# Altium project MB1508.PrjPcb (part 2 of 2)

## Sheet Peripherals.SchDoc: Peripherals
size A4; Date: Not used; ApprovedBy: Not used; CheckedBy: Not used; Author: Not used; CompanyName: STMicroelectronics; DrawnBy: Not used; Engineer: Not used; Organization: Not used; Address1: Not used; Address2: Not used; Address3: Not used; Address4: Not used; DocumentNumber: Not used; Revision: Not used; SheetNumber: 8; SheetTotal: 11
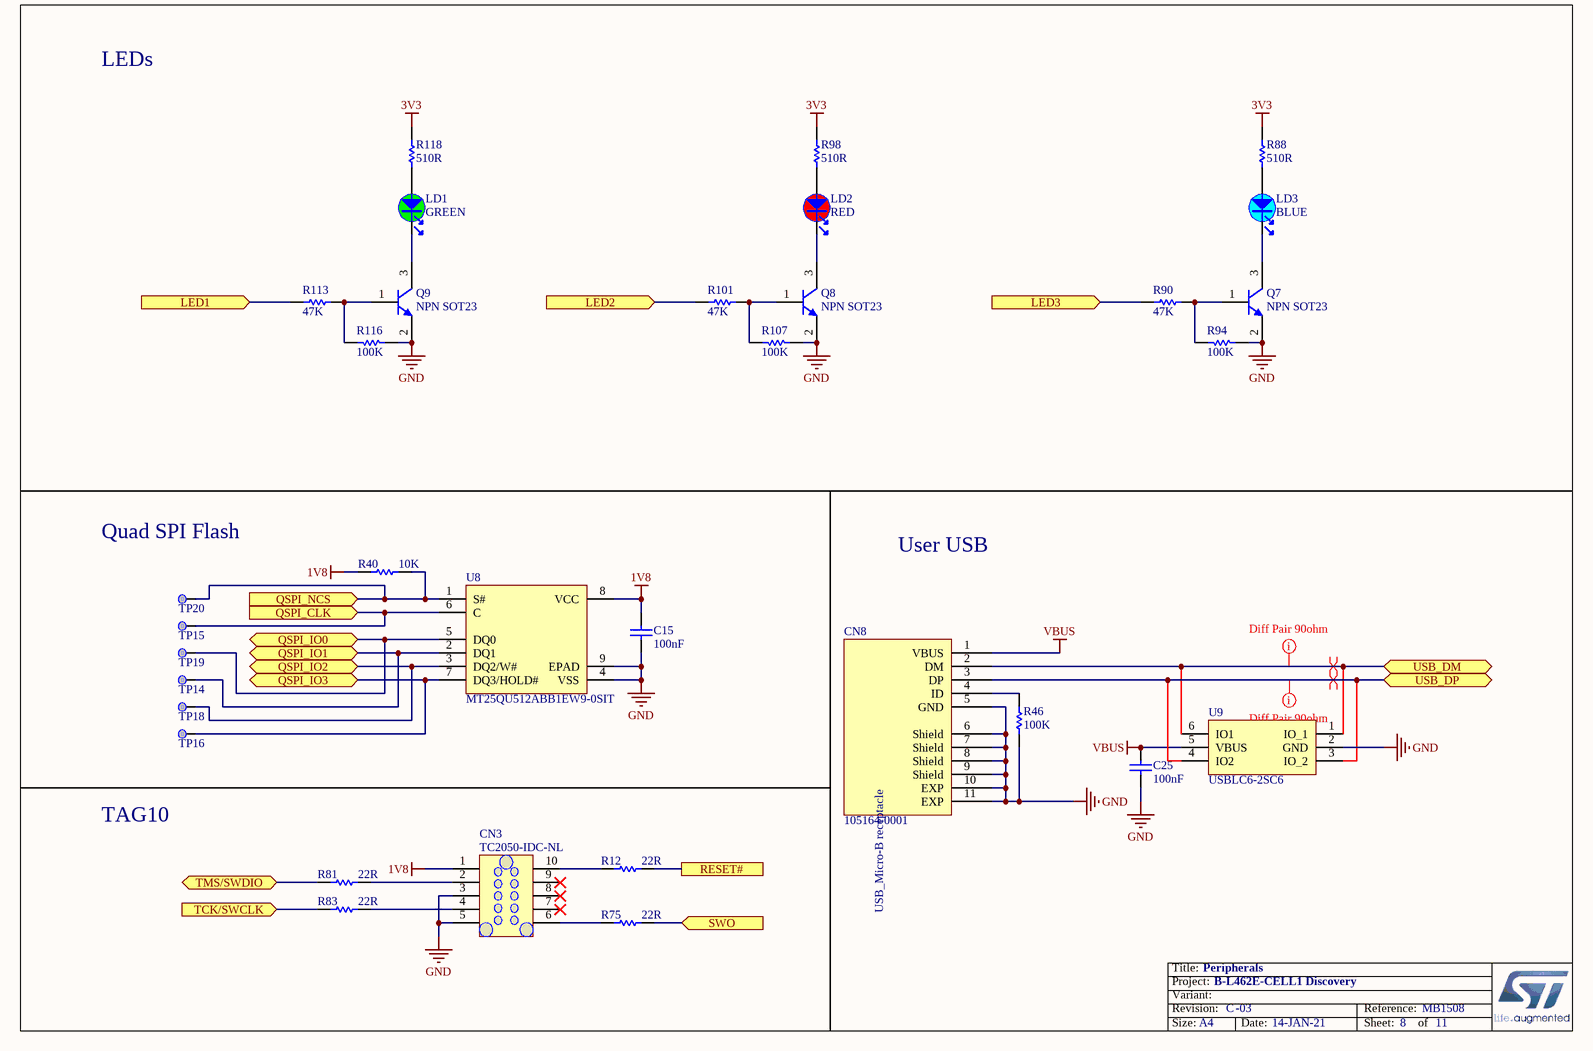
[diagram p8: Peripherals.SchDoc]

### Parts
C15  value 100nF  [C0603]  (hidden comment: Capacitor)
C25  value 100nF  [C0603]  (hidden comment: Capacitor)
CN3  value TC2050-IDC-NL  [CON_TAG-C_TC2050-IDC-NL]  (hidden comment: Tag-10-C)
CN8  value 105164-0001  [CON_USBMICROB_MOLEX_105164-0001_H2P45]  (hidden comment: USB_uB_105164-0001)
LD1  value GREEN  [LED_0603_GREEN_H0P8]  (hidden comment: LED_green)
LD2  value RED  [LED_0603_RED_H0P4]  (hidden comment: LED_red)
LD3  value BLUE  [LED_0603_OSRAM_LB-Q39G-L2OO-35-1_BLUE_1A2K_H0P4]  (hidden comment: LED_blue)
Q7  value NPN SOT23  [NPN_SOT23]  (hidden comment: 9013-SOT23)
Q8  value NPN SOT23  [NPN_SOT23]  (hidden comment: 9013-SOT23)
Q9  value NPN SOT23  [NPN_SOT23]  (hidden comment: 9013-SOT23)
R12  value 22R  [R0603]  (hidden comment: Resistor)
R40  value 10K  [R0603]  (hidden comment: Resistor)
R46  value 100K  [R0603]  (hidden comment: Resistor)
R75  value 22R  [R0603]  (hidden comment: Resistor)
R81  value 22R  [R0603]  (hidden comment: Resistor)
R83  value 22R  [R0603]  (hidden comment: Resistor)
R88  value 510R  [R0603]  (hidden comment: Resistor)
R90  value 47K  [R0603]  (hidden comment: Resistor)
R94  value 100K  [R0603]  (hidden comment: Resistor)
R98  value 510R  [R0603]  (hidden comment: Resistor)
R101  value 47K  [R0603]  (hidden comment: Resistor)
R107  value 100K  [R0603]  (hidden comment: Resistor)
R113  value 47K  [R0603]  (hidden comment: Resistor)
R116  value 100K  [R0603]  (hidden comment: Resistor)
R118  value 510R  [R0603]  (hidden comment: Resistor)
TP14  Test Point  [TP_SMD_1MM]  (value not drawn)  (no BOM)
TP15  Test Point  [TP_SMD_1MM]  (value not drawn)  (no BOM)
TP16  Test Point  [TP_SMD_1MM]  (value not drawn)  (no BOM)
TP18  Test Point  [TP_SMD_1MM]  (value not drawn)  (no BOM)
TP19  Test Point  [TP_SMD_1MM]  (value not drawn)  (no BOM)
TP20  Test Point  [TP_SMD_1MM]  (value not drawn)  (no BOM)
U8  MT25QU512ABB1EW9-0SIT  [ICC_W-PDFN-8_8X6_P127]
U9  USBLC6-2SC6  [ESD_SOT23-6L]

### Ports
LED1 (in), LED2 (in), LED3 (in), QSPI_CLK (in), QSPI_IO0 (bidir), QSPI_IO1 (bidir), QSPI_IO2 (bidir), QSPI_IO3 (bidir), QSPI_NCS (in), RESET#, SWO (in), TCK/SWCLK (in), TMS/SWDIO (bidir), USB_DM (bidir), USB_DP (bidir)

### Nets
1V8: C15.2 CN3.1 R40.1 U8.8(VCC)
3V3: R88.2 R98.2 R118.2
GND: C15.1 C25.1 CN3.3 CN3.5 CN8.5(GND) CN8.6(Shield) CN8.7(Shield) CN8.8(Shield) CN8.9(Shield) CN8.10(EXP) CN8.11(EXP) Q7.2(E) Q8.2(E) Q9.2(E) R46.2 R94.1 R107.1 R116.1 U8.4(VSS) U8.9(EPAD) U9.2(GND)
VBUS: C25.2 CN8.1(VBUS) U9.5(VBUS)
NRST: R12.2 ; port RESET#
PA6: TP16.1 U8.7(DQ3/HOLD#) ; port QSPI_IO3
PA7: TP18.1 U8.3(DQ2/W#) ; port QSPI_IO2
PA11: CN8.2(DM) U9.1(IO_1) U9.6(IO1) ; port USB_DM
PA12: CN8.3(DP) U9.3(IO_2) U9.4(IO2) ; port USB_DP
PA13: R81.1 ; port TMS/SWDIO
PA14: R83.1 ; port TCK/SWCLK
PB0: TP14.1 U8.2(DQ1) ; port QSPI_IO1
PB1: TP19.1 U8.5(DQ0) ; port QSPI_IO0
PB10: TP15.1 U8.6(C) ; port QSPI_CLK
PB14: R90.2 ; port LED3
PB15: R101.2 ; port LED2
PC6: R113.2 ; port LED1
QSPI_NCS: R40.2 TP20.1 U8.1(S#) ; port QSPI_NCS
SWO: R75.2 ; port SWO
NetCN3_2: CN3.2 R81.2
NetCN3_4: CN3.4 R83.2
NetCN3_6: CN3.6 R75.1
NetCN3_10: CN3.10 R12.1
NetCN8_4: CN8.4(ID) R46.1
NetLD1_1: LD1.1 R118.1
NetLD1_2: LD1.2 Q9.3(C)
NetLD2_1: LD2.1 R98.1
NetLD2_2: LD2.2 Q8.3(C)
NetLD3_1: LD3.1 R88.1
NetLD3_2: LD3.2 Q7.3(C)
NetQ7_1: Q7.1(B) R90.1 R94.2
NetQ8_1: Q8.1(B) R101.1 R107.2
NetQ9_1: Q9.1(B) R113.1 R116.2

Not connected (* = marked no-connect by the designer): CN3 7* 8* 9*

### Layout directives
mark named Diff Pair 90ohm: PA11, PA12
differential pair: PA11, PA12

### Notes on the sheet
- LEDs
- Quad SPI Flash
- User USB
- TAG10

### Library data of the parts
C15 = MCD-00237: Capacitor, MLCC, 100nF, 6V3, X5R, +/-10%, 0603, T=0,8mm; Part_Preference: Not recommended; Manufacturer: YAGEO; Manufacturer_Part_Number: CC0603KRX5R5BB104
C25 = MCD-00211: Capacitor, MLCC, 100nF, 16V, X7R, +/-10%, 0603, T=0,8mm; Part_Preference: Recommended; Manufacturer: YAGEO; Manufacturer_Part_Number: CC0603KRX7R7BB104; Order_Code_RS: 669-8763
CN3 = MCD-00031: Tag_Connector Header, 10x2, No legs; Part_Preference: Recommended; Manufacturer: TAG-CONNECT LLC; Manufacturer_Part_Number: TC2050-IDC-NL-FP
CN8 = MCD-01698: Micro-USB B Receptacle without Flange, Top Mount, Surface Mount, Lead-Free; Part_Type: Connector; Part_Preference: Recommended; Manufacturer: MOLEX
LD1 = MCD-00320: LED, Green, 0603; Part_Type: Display; Part_Preference: Not recommended; Manufacturer: EVERLIGHT; Manufacturer_Part_Number: 19-213SYGC/S530-E2/TR8
LD2 = MCD-00322: LED, Red, 0603; Part_Type: Display; Part_Preference: Recommended; Manufacturer: EVERLIGHT; Manufacturer_Part_Number: 19-217/R6C-AL1M2VY/3T
LD3 = MCD-00585: LED Blue, 0603 SMD, Forward Voltage Min=2,8V, Max=3,8V; Part_Type: Display; Part_Preference: Recommended; Manufacturer: OSRAM OPTO SEMICONDUCTORS; Manufacturer_Part_Number: LB Q39G-L2OO-35-1; Alternate_Manufacturer: EVERLIGHT; Alternate_Manufacturer_Part_Number: 19-217-BHC-ZL1M2RY-3T-V4; Order_Code_RS: 9148643
Q7-Q9 = MCD-00073: NPN Bipolar Transistor; Part_Type: IC; Part_Preference: Recommended; Manufacturer: ON SEMICONDUCTOR; Manufacturer_Part_Number: BSR14; Alternate_Manufacturer_Part_Number: MMBT2222LT1G / MMBT2222ALT1G / MMBT2222ALT3G
R12 R75 R81 R83 = MCD-00190: Resistor,22R,0603,1%,1/10W; Part_Preference: Not recommended; Manufacturer: YAGEO; Manufacturer_Part_Number: RC0603FR-0722RL
R40 = MCD-00220: Resistor,10K,0603,1%,1/10W; Part_Preference: Recommended; Manufacturer: YAGEO; Manufacturer_Part_Number: RC0603FR-0710KL
R46 R94 R107 R116 = MCD-00223: Resistor,100K,0603,1%,1/10W; Part_Preference: Recommended; Manufacturer: YAGEO; Manufacturer_Part_Number: RC0603FR-07100KL
R88 R98 R118 = MCD-00225: Resistor,510R,0603,1%,1/10W; Part_Preference: Recommended; Manufacturer: YAGEO; Manufacturer_Part_Number: RC0603FR-07510RL
R90 R101 R113 = MCD-00222: Resistor,47K,0603,1%,1/10W; Part_Preference: Recommended; Manufacturer: YAGEO; Manufacturer_Part_Number: RC0603FR-0747KL
TP14-TP16 TP18-TP20 = MCD-00074: Test Point 1mm; Part_Type: Misc; Part_Preference: Recommended
U8 = MCD-01749: 512Mb, 1.8V Multiple I/O Serial Flash Memory; BMS_Part_Number: 9171981; Part_Type: IC; Part_Preference: Recommended; Manufacturer: MICRON
U9 = MCD-00163: Very low capacitance ESD protection; BMS_Part_Number: 9151075; Part_Type: IC; Part_Preference: Recommended; Manufacturer: STMICROELECTRONICS; Manufacturer_HQ_COO: EU

## Sheet Sensors & LCD.SchDoc: Sensors & LCD
size A4; Date: Not used; ApprovedBy: Not used; CheckedBy: Not used; Author: Not used; CompanyName: STMicroelectronics; DrawnBy: Not used; Engineer: Not used; Organization: Not used; Address1: Not used; Address2: Not used; Address3: Not used; Address4: Not used; DocumentNumber: Not used; Revision: Not used; SheetNumber: 9; SheetTotal: 11
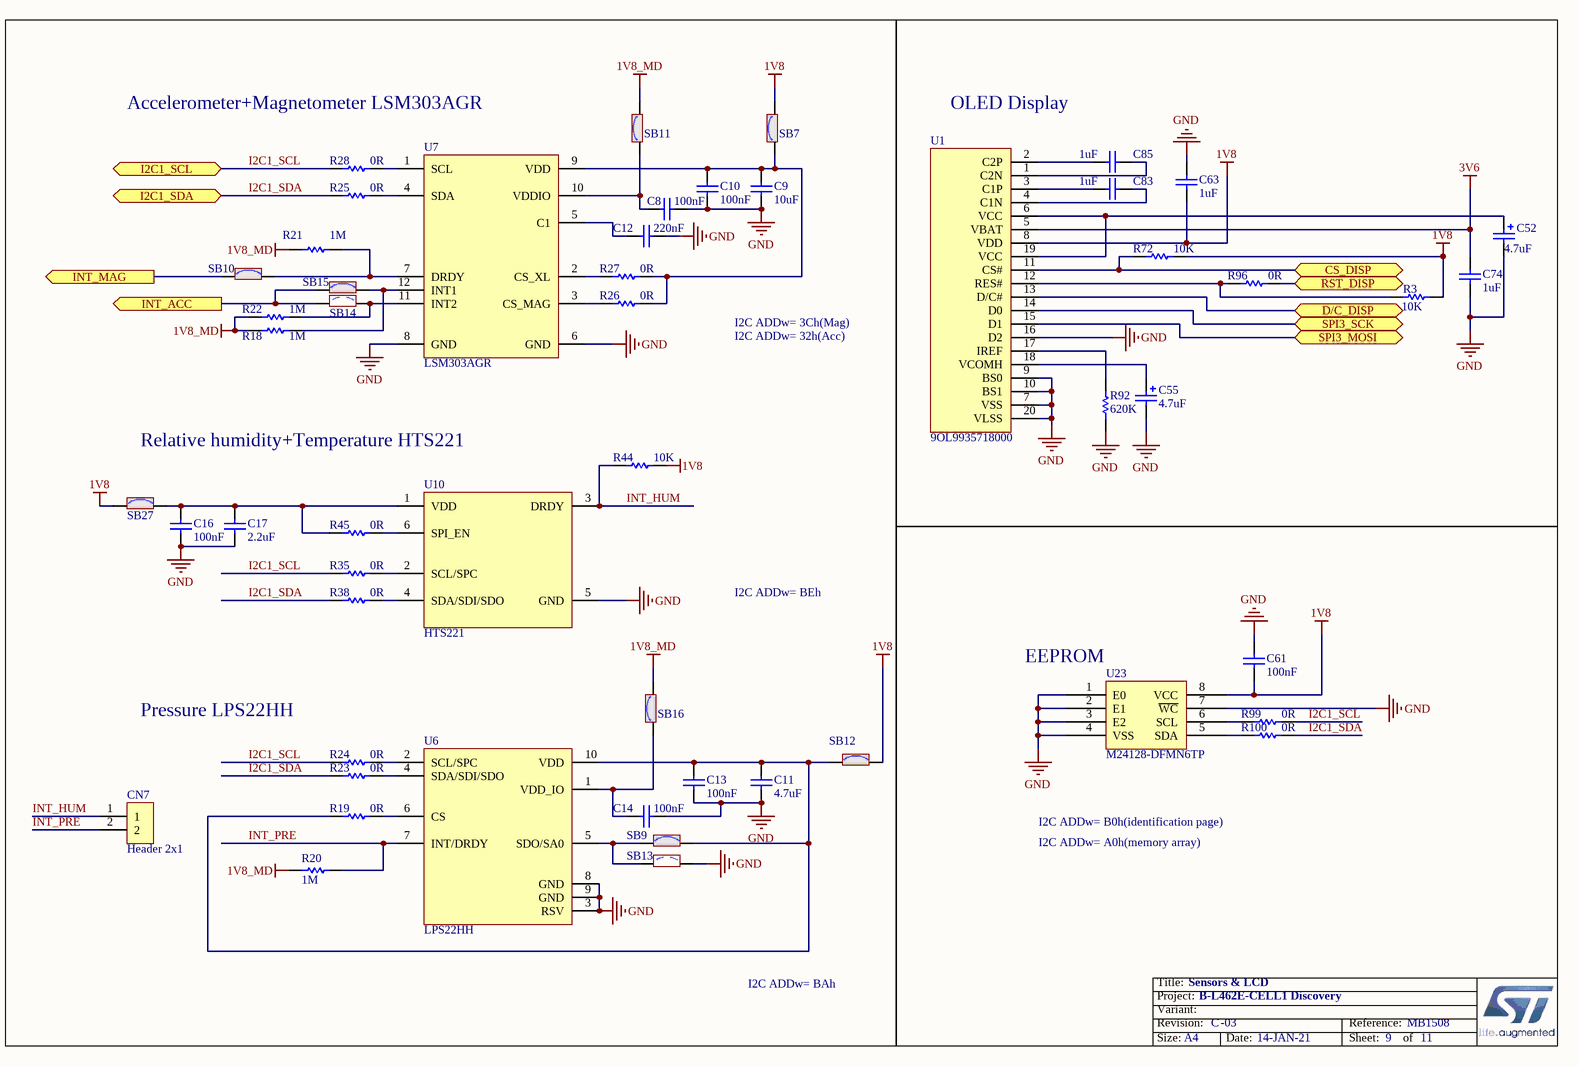
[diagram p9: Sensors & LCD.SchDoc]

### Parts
C8  value 100nF  [C0603]  (hidden comment: Capacitor)
C9  value 10uF  [C0603]  (hidden comment: Capacitor)
C10  value 100nF  [C0603]  (hidden comment: Capacitor)
C11  value 4.7uF  [C0603]  (hidden comment: Capacitor)
C12  value 220nF  [C0402]  (hidden comment: Capacitor)
C13  value 100nF  [C0603]  (hidden comment: Capacitor)
C14  value 100nF  [C0603]  (hidden comment: Capacitor)
C16  value 100nF  [C0603]  (hidden comment: Capacitor)
C17  value 2.2uF  [C0603]  (hidden comment: Capacitor)
C52  value 4.7uF  [CPOL_TAJ-A_1206_H180]  (hidden comment: Cap_POL_TANA)
C55  value 4.7uF  [CPOL_TAJ-A_1206_H180]  (hidden comment: Cap_POL_TANA)
C61  value 100nF  [C0603]  (hidden comment: Capacitor)
C63  value 1uF  [C0603]  (hidden comment: Capacitor)
C74  value 1uF  [C0603]  (hidden comment: Capacitor)
C83  value 1uF  [C0603]  (hidden comment: Capacitor)
C85  value 1uF  [C0603]  (hidden comment: Capacitor)
CN7  Header 2x1  [CON_SAMTEC_TSW-102-08-G-S]
R3  value 10K  [R0603]  (hidden comment: Resistor)
R18  value 1M  [R0603]  (hidden comment: Resistor)
R19  value 0R  [R0603]  (hidden comment: Resistor)
R20  value 1M  [R0603]  (hidden comment: Resistor)
R21  value 1M  [R0603]  (hidden comment: Resistor)
R22  value 1M  [R0603]  (hidden comment: Resistor)
R23  value 0R  [R0603]  (hidden comment: Resistor)
R24  value 0R  [R0603]  (hidden comment: Resistor)
R25  value 0R  [R0603]  (hidden comment: Resistor)
R26  value 0R  [R0603]  (hidden comment: Resistor)
R27  value 0R  [R0603]  (hidden comment: Resistor)
R28  value 0R  [R0603]  (hidden comment: Resistor)
R35  value 0R  [R0603]  (hidden comment: Resistor)
R38  value 0R  [R0603]  (hidden comment: Resistor)
R44  value 10K  [R0603]  (hidden comment: Resistor)
R45  value 0R  [R0603]  (hidden comment: Resistor)
R72  value 10K  [R0603]  (hidden comment: Resistor)
R92  value 620K  [R0603]  (hidden comment: Resistor)
R96  value 0R  [R0603]  (hidden comment: Resistor)
R99  value 0R  [R0603]  (hidden comment: Resistor)
R100  value 0R  [R0603]  (hidden comment: Resistor)
SB7  SB_ON  [SOLDER-BRIDGE_R0603-0R]  (value not drawn)
SB9  SB_ON  [SOLDER-BRIDGE_R0603-0R]  (value not drawn)
SB10  SB_ON  [SOLDER-BRIDGE_R0603-0R]  (value not drawn)
SB11  SB_ON  [SOLDER-BRIDGE_R0603-0R]  (value not drawn)
SB12  SB_ON  [SOLDER-BRIDGE_R0603-0R]  (value not drawn)
SB13  SB_OFF  [SOLDER-BRIDGE_R0603-0R]  (value not drawn)
SB14  SB_OFF  [SOLDER-BRIDGE_R0603-0R]  (value not drawn)
SB15  SB_ON  [SOLDER-BRIDGE_R0603-0R]  (value not drawn)
SB16  SB_ON  [SOLDER-BRIDGE_R0603-0R]  (value not drawn)
SB27  SB_ON  [SOLDER-BRIDGE_R0603-0R]  (value not drawn)
U1  value 9OL9935718000  [OLED_RITDISPLAY_9OL9935718000]  (hidden comment: OLED_RITDISPLAY_9OL9935718000)
U6  LPS22HH  [ICC_HLGA10_2X2_P050]
U7  LSM303AGR  [ICC_LGA12_2X2_P050]
U10  HTS221  [ICC_HLGA6_2X2_P075-1]
U23  M24128-DFMN6TP  [ICC_SO8_5X4_P127]

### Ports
CS_DISP (bidir), D/C_DISP (bidir), I2C1_SCL (bidir), I2C1_SDA (bidir), INT_ACC (out), INT_MAG (out), RST_DISP (bidir), SPI3_MOSI (bidir), SPI3_SCK (bidir)

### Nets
1V8: C61.1 C63.1 R3.1 R44.2 R72.2 SB7.2 SB12.2 SB27.1 U1.8(VDD) U23.8(VCC)
1V8_MD: R18.1 R20.1 R21.1 R22.1 SB11.2 SB16.2
3V6: C74.2 U1.5(VBAT)
GND: C8.1 C9.1 C10.1 C11.2 C12.2 C13.1 C14.1 C16.1 C17.2 C52.2 C55.2 C61.2 C63.2 C74.1 R92.1 SB13.2 U1.7(VSS) U1.9(BS0) U1.10(BS1) U1.16(D2) U1.20(VLSS) U6.3(RSV) U6.8(GND) U6.9(GND) U7.6(GND) U7.8(GND) U10.5(GND) U23.1(E0) U23.2(E1) U23.3(E2) U23.4(VSS) U23.7(~{WC})
I2C1_SCL: R24.1 R28.1 R35.1 R99.2 ; port I2C1_SCL
I2C1_SDA: R23.1 R25.1 R38.1 R100.2 ; port I2C1_SDA
INT_HUM: CN7.1 R44.1 U10.3(DRDY)
INT_PRE: CN7.2 R20.2 U6.7(INT/DRDY)
PB2_R: R72.1 U1.11(CS#) ; port CS_DISP
PC2: SB14.1 SB15.1 ; port INT_ACC
PC3: SB10.1 ; port INT_MAG
PC10: U1.14(D0) ; port SPI3_SCK
PC11: U1.13(D/C#) ; port D/C_DISP
PC12: U1.15(D1) ; port SPI3_MOSI
PH1: R96.2 ; port RST_DISP
NetC8_2: C8.2 SB11.1 U7.10(VDDIO)
NetC9_2: C9.2 C10.2 R26.2 R27.2 SB7.1 U7.9(VDD)
NetC11_1: C11.1 C13.2 R19.1 SB9.2 SB12.1 U6.10(VDD)
NetC12_1: C12.1 U7.5(C1)
NetC14_2: C14.2 SB16.1 U6.1(VDD_IO)
NetC16_2: C16.2 C17.1 R45.1 SB27.2 U10.1(VDD)
NetC52_1: C52.1 U1.6(VCC) U1.19(VCC)
NetC55_1: C55.1 U1.18(VCOMH)
NetC83_1: C83.1 U1.3(C1P)
NetC83_2: C83.2 U1.4(C1N)
NetC85_1: C85.1 U1.2(C2P)
NetC85_2: C85.2 U1.1(C2N)
NetR3_2: R3.2 R96.1 U1.12(RES#)
NetR18_2: R18.2 SB15.2 U7.12(INT1)
NetR19_2: R19.2 U6.6(CS)
NetR21_2: R21.2 SB10.2 U7.7(DRDY)
NetR22_2: R22.2 SB14.2 U7.11(INT2)
NetR23_2: R23.2 U6.4(SDA/SDI/SDO)
NetR24_2: R24.2 U6.2(SCL/SPC)
NetR25_2: R25.2 U7.4(SDA)
NetR26_1: R26.1 U7.3(CS_MAG)
NetR27_1: R27.1 U7.2(CS_XL)
NetR28_2: R28.2 U7.1(SCL)
NetR35_2: R35.2 U10.2(SCL/SPC)
NetR38_2: R38.2 U10.4(SDA/SDI/SDO)
NetR45_2: R45.2 U10.6(SPI_EN)
NetR92_2: R92.2 U1.17(IREF)
NetR99_1: R99.1 U23.6(SCL)
NetR100_1: R100.1 U23.5(SDA)
NetSB9_1: SB9.1 SB13.1 U6.5(SDO/SA0)

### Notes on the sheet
- Accelerometer+Magnetometer LSM303AGR
- OLED Display
- I2C ADDw= 3Ch(Mag)
- I2C ADDw= 32h(Acc)
- Relative humidity+Temperature HTS221
- I2C ADDw= BEh
- (near U23) EEPROM
- Pressure LPS22HH
- I2C ADDw= A0h(memory array)
- I2C ADDw= B0h(identification page)
- I2C ADDw= BAh

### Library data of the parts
C8 C10 C13 C14 C16 C61 = MCD-00237: as C15 on sheet Peripherals
C9 = MCD-00243: Capacitor, MLCC, 10uF, 6V3, X5R, +/-10%, 0603, T=0,8mm; Part_Preference: Recommended; Manufacturer: YAGEO; Manufacturer_Part_Number: CC0603KRX5R5BB106
C11 = MCD-00009: Capacitor, MLCC, 4.7uF, 16V, X5R, +/-10%, 0603, T=0.8mm; Part_Preference: Recommended; Manufacturer: YAGEO; Manufacturer_Part_Number: CC0603KRX5R7BB475
C12 = MCD-00602: Capacitor, MLCC, 220nF, 16V, X7R, +/-10%, ,0402, T=0,5mm; Part_Preference: Recommended; Manufacturer: TDK; Manufacturer_Part_Number: C1005X7R1C224K050BE
C17 = MCD-00012: Capacitor, MLCC, 2.2uF, 10V, X5R, +/- 10%, 0603, T=0,8mm; BMS_Part_Number: 9142010; Part_Preference: Recommended; Manufacturer: YAGEO; Manufacturer_Part_Number: CC0603KRX5R6BB225; Alternate_Manufacturer: KEMET; Alternate_Manufacturer_Part_Number: C0603C225K8PACTU
C52 C55 = MCD-00007: Capacitor, Tantalum, 4.7uF, 16V, 4ohms, +/-10%, pkg Type_A (3216 metric), T=1.6mm; Part_Preference: Recommended; Manufacturer: AVX; Manufacturer_Part_Number: TAJA475K016R; Order_Code_RS: 464-9132
C63 C74 C83 C85 = MCD-00010: Capacitor, MLCC, 1uF, 16V, X5R, +/-10%, 0603, T=0,8mm; Part_Preference: Recommended; Manufacturer: YAGEO; Manufacturer_Part_Number: CC0603KRX5R7BB105
CN7 = MCD-01581: Header 2x1, 2.54mm, VR, TH, height 5.84mm/5.08 mm, height total 13.46 mm; Part_Type: Connector; Part_Preference: Recommended; Manufacturer: SAMTEC; Manufacturer_Part_Number: TSW-102-08-G-S
R3 R44 R72 = MCD-00220: as R40 on sheet Peripherals
R18 R20-R22 = MCD-00257: Resistor,1M,0603,1%,1/10W; Part_Preference: Recommended; Manufacturer: YAGEO; Manufacturer_Part_Number: RC0603FR-071ML
R19 R23-R28 R35 R38 R45 R96 R99 R100 = MCD-00056: Resistor,0R,0603,5%,1/10W; Part_Preference: Recommended; Manufacturer: YAGEO; Manufacturer_Part_Number: RC0603JR-070RL
R92 = MCD-00506: Resistor,620K,0603,1%,1/10W; Part_Preference: Recommended; Manufacturer: YAGEO; Manufacturer_Part_Number: RC0603FR-07620KL
SB7 SB9-SB12 SB15 SB16 SB27 = MCD-00071: Solder Bridge ON; Part_Type: Misc; Part_Preference: Recommended; Manufacturer: YAGEO; Manufacturer_Part_Number: RC0603JR-070RL
SB13 SB14 = MCD-00072: Solder Bridge OFF; Part_Type: Misc; Part_Preference: Recommended; Manufacturer: YAGEO; Manufacturer_Part_Number: RC0603JR-070RL
U1 = MCD-01925: 128*64 Dots 20-pin OLED display; Part_Preference: Recommended; Alternate_Manufacturer_Part_Number: 9OL9935701000
U6 = MCD-01702: High-performance MEMS nano pressure sensor:260-1260 hPa absolute digital output barometer; Part_Type: IC; Part_Preference: Recommended; Manufacturer: STMICROELECTRONICS; Manufacturer_HQ_COO: EU; Component_Country_Of_Origin: France, Malta
U7 = MCD-00709: 3D accelerometer and 3D magnetometer; BMS_Part_Number: 9177057; Part_Type: IC; Part_Preference: Recommended; Manufacturer: STMICROELECTRONICS; Manufacturer_HQ_COO: EU
U10 = MCD-01447: Capacitive digital sensor for relative humidity and temperature; BMS_Part_Number: 9188011; Part_Type: IC; Part_Preference: Recommended; Manufacturer: STMICROELECTRONICS; Manufacturer_HQ_COO: EU
U23 = MCD-00293: I2C memory; BMS_Part_Number: 9175659; Part_Type: IC; Part_Preference: Recommended; Manufacturer: STMICROELECTRONICS; Manufacturer_HQ_COO: EU

## Sheet ST_LINK_V2-1.SchDoc: ST_LINK_V2-1
size A4; Date: Not used; ApprovedBy: Not used; CheckedBy: Not used; Author: Not used; CompanyName: STMicroelectronics; DrawnBy: Not used; Engineer: Not used; Organization: Not used; Address1: Not used; Address2: Not used; Address3: Not used; Address4: Not used; DocumentNumber: Not used; Revision: Not used; SheetNumber: 10; SheetTotal: 11
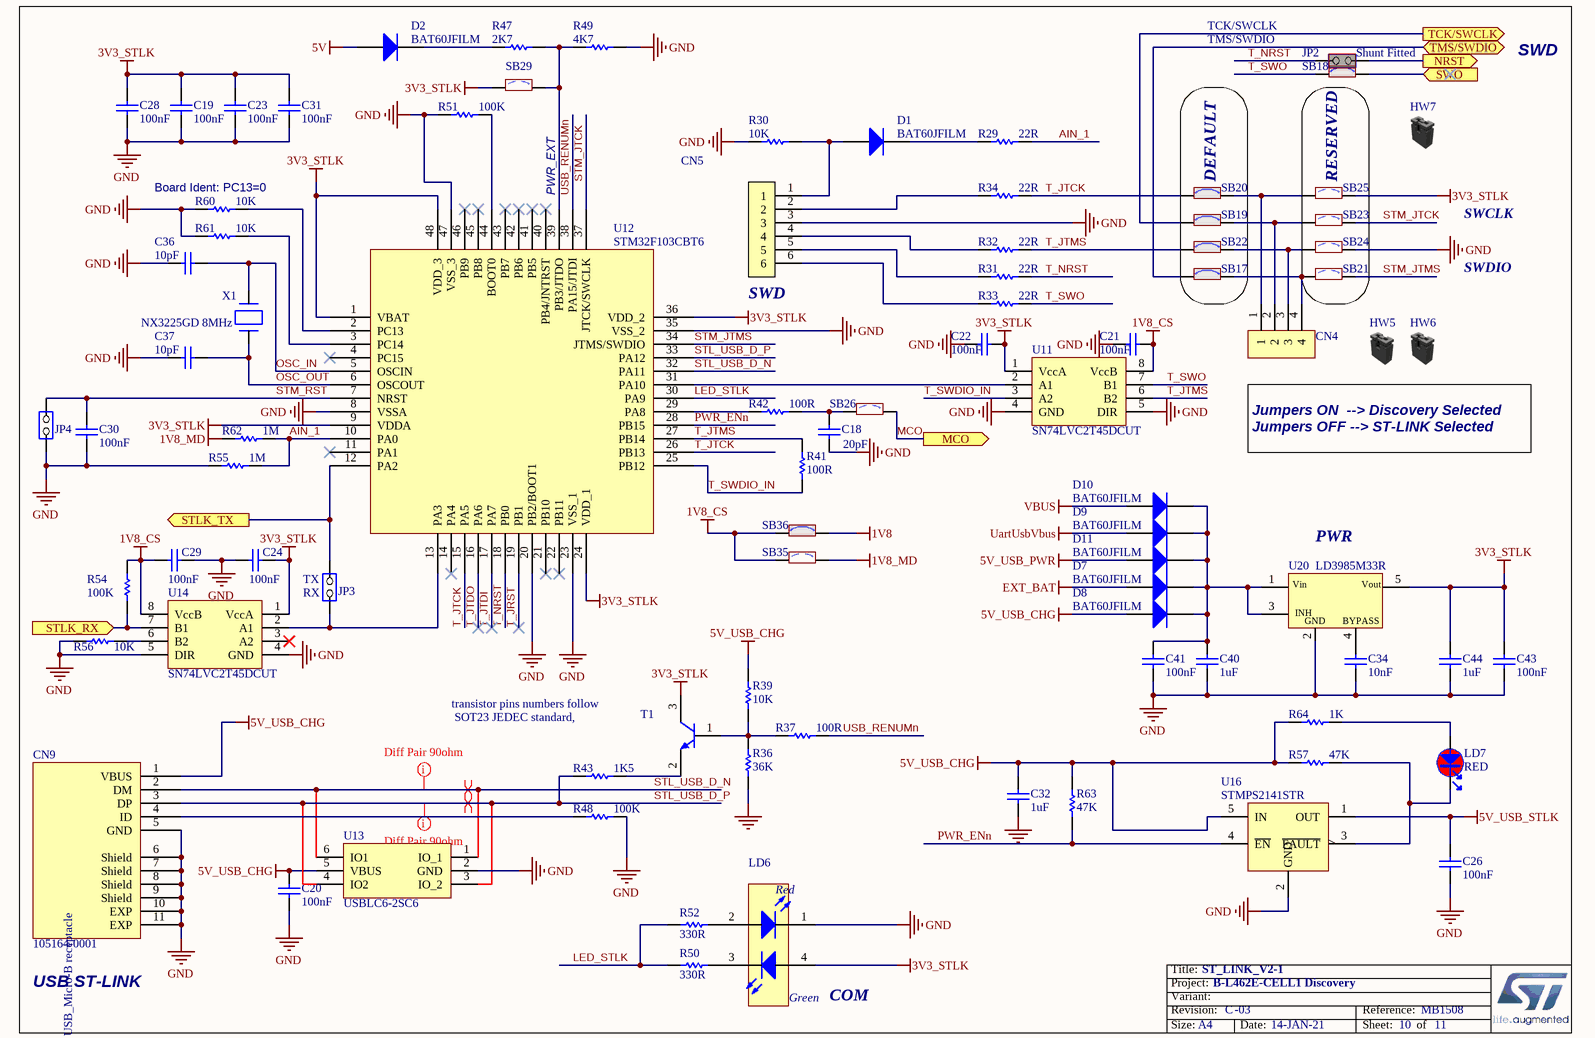
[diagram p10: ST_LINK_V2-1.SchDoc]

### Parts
C18  value 20pF  [C0603]  (hidden comment: Capacitor)
C19  value 100nF  [C0603]  (hidden comment: Capacitor)
C20  value 100nF  [C0603]  (hidden comment: Capacitor)
C21  value 100nF  [C0603]  (hidden comment: Capacitor)
C22  value 100nF  [C0603]  (hidden comment: Capacitor)
C23  value 100nF  [C0603]  (hidden comment: Capacitor)
C24  value 100nF  [C0603]  (hidden comment: Capacitor)
C26  value 100nF  [C0603]  (hidden comment: Capacitor)
C28  value 100nF  [C0603]  (hidden comment: Capacitor)
C29  value 100nF  [C0603]  (hidden comment: Capacitor)
C30  value 100nF  [C0603]  (hidden comment: Capacitor)
C31  value 100nF  [C0603]  (hidden comment: Capacitor)
C32  value 1uF  [C0603]  (hidden comment: Capacitor)
C34  value 10nF  [C0603]  (hidden comment: Capacitor)
C36  value 10pF  [C0603]  (hidden comment: Capacitor)
C37  value 10pF  [C0603]  (hidden comment: Capacitor)
C40  value 1uF  [C0603]  (hidden comment: Capacitor)
C41  value 100nF  [C0603]  (hidden comment: Capacitor)
C43  value 100nF  [C0603]  (hidden comment: Capacitor)
C44  value 1uF  [C0603]  (hidden comment: Capacitor)
CN4  Header 4x1  [CON_988-JIUBABA_PHFS25-11-04-G0B115-T-1]  (value not drawn)
CN5  Header 6x1  [CON_988-JIUBABA_PHFS25-11-06-G0B115-T-1]  (value not drawn)
CN9  value 105164-0001  [CON_USBMICROB_MOLEX_105164-0001_H2P45]  (hidden comment: USB_uB_105164-0001)
D1  BAT60JFILM  [DIO_SOD323]
D2  BAT60JFILM  [DIO_SOD323]
D7  BAT60JFILM  [DIO_SOD323]
D8  BAT60JFILM  [DIO_SOD323]
D9  BAT60JFILM  [DIO_SOD323]
D10  BAT60JFILM  [DIO_SOD323]
D11  BAT60JFILM  [DIO_SOD323]
HW5  Shunt Black 2.54mm  (value not drawn)  (mechanical)
HW6  Shunt Black 2.54mm  (value not drawn)  (mechanical)
HW7  Shunt Black 2.54mm  (value not drawn)  (mechanical)
JP2  value Shunt Fitted  [CON_SAMTEC_TSW-102-07-G-S]  (hidden comment: Jumper_Header 2x1 Fitted)
JP3  Jumper_Header 2x1  [CON_SAMTEC_TSW-102-07-G-S]  (value not drawn)
JP4  Jumper_Header 2x1  [CON_SAMTEC_TSW-102-07-G-S]  (value not drawn)
LD6  LD_BICOLOR_CMS  [LED_BI-GR_HSMF-A201-A00J1]  (value not drawn)
LD7  value RED  [LED_0603_RED]  (hidden comment: LED_red)
R29  value 22R  [R0603]  (hidden comment: Resistor)
R30  value 10K  [R0603]  (hidden comment: Resistor)
R31  value 22R  [R0603]  (hidden comment: Resistor)
R32  value 22R  [R0603]  (hidden comment: Resistor)
R33  value 22R  [R0603]  (hidden comment: Resistor)
R34  value 22R  [R0603]  (hidden comment: Resistor)
R36  value 36K  [R0603]  (hidden comment: Resistor)
R37  value 100R  [R0603]  (hidden comment: Resistor)
R39  value 10K  [R0603]  (hidden comment: Resistor)
R41  value 100R  [R0603]  (hidden comment: Resistor)
R42  value 100R  [R0603]  (hidden comment: Resistor)
R43  value 1K5  [R0603]  (hidden comment: Resistor)
R47  value 2K7  [R0603]  (hidden comment: Resistor)
R48  value 100K  [R0603]  (hidden comment: Resistor)
R49  value 4K7  [R0603]  (hidden comment: Resistor)
R50  value 330R  [R0603]  (hidden comment: Resistor)
R51  value 100K  [R0603]  (hidden comment: Resistor)
R52  value 330R  [R0603]  (hidden comment: Resistor)
R54  value 100K  [R0603]  (hidden comment: Resistor)
R55  value 1M  [R0603]  (hidden comment: Resistor)
R56  value 10K  [R0603]  (hidden comment: Resistor)
R57  value 47K  [R0603]  (hidden comment: Resistor)
R60  value 10K  [R0603]  (hidden comment: Resistor)
R61  value 10K  [R0603]  (hidden comment: Resistor)
R62  value 1M  [R0603]  (hidden comment: Resistor)
R63  value 47K  [R0603]  (hidden comment: Resistor)
R64  value 1K  [R0603]  (hidden comment: Resistor)
SB17  SB_ON  [SOLDER-BRIDGE_R0603-0R]  (value not drawn)
SB18  SB_ON  [SOLDER-BRIDGE_R0603-0R]  (value not drawn)
SB19  SB_ON  [SOLDER-BRIDGE_R0603-0R]  (value not drawn)
SB20  SB_ON  [SOLDER-BRIDGE_R0603-0R]  (value not drawn)
SB21  SB_OFF  [SOLDER-BRIDGE_R0603-0R]  (value not drawn)
SB22  SB_ON  [SOLDER-BRIDGE_R0603-0R]  (value not drawn)
SB23  SB_OFF  [SOLDER-BRIDGE_R0603-0R]  (value not drawn)
SB24  SB_OFF  [SOLDER-BRIDGE_R0603-0R]  (value not drawn)
SB25  SB_OFF  [SOLDER-BRIDGE_R0603-0R]  (value not drawn)
SB26  SB_OFF  [SOLDER-BRIDGE_R0603-0R]  (value not drawn)
SB29  SB_OFF  [SOLDER-BRIDGE_R0603-0R]  (value not drawn)
SB35  SB_OFF  [SOLDER-BRIDGE_R0603-0R]  (value not drawn)
SB36  SB_ON  [SOLDER-BRIDGE_R0603-0R]  (value not drawn)
T1  9013-SOT23  [NPN_SOT23]  (value not drawn)
U11  SN74LVC2T45DCUT  [ICC_VSSOP8_DCU_R-PDSO-G8_2X2P30_P050]
U12  STM32F103CBT6  [ICC_LQFP48_7X7_P050]
U13  USBLC6-2SC6  [ESD_SOT23-6L]
U14  SN74LVC2T45DCUT  [ICC_VSSOP8_DCU_R-PDSO-G8_2X2P30_P050]
U16  STMPS2141STR  [MOS_SOT23-5L]
U20  LD3985M33R  [REG_SOT23-5L]
X1  value NX3225GD 8MHz  [CRY_NX3225GD_2P]  (hidden comment: XTAL_2_PINS)

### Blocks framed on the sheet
DEFAULT: SB17 SB19 SB20 SB22
RESERVED: SB21 SB23-SB25

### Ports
MCO (out), NRST (out), STLK_RX (in), STLK_TX (out), SWO (in), TCK/SWCLK (out), TMS/SWDIO (bidir)

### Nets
1V8: SB36.2
1V8_CS: C21.1 C29.1 R54.2 SB35.1 SB36.1 U11.8(VccB) U14.8(VccB)
1V8_MD: R62.1 SB35.2
3V3_STLK: C19.2 C22.2 C23.2 C24.2 C28.2 C31.2 C43.2 C44.2 LD6.4(YellowGreen_anode) SB25.2 SB29.1 T1.3(C) U11.1(VccA) U12.1(VBAT) U12.9(VDDA) U12.24(VDD_1) U12.36(VDD_2) U12.48(VDD_3) U14.1(VccA) U20.5(Vout)
5V: D2.1(A)
5V_USB_CHG: C20.2 C32.1 CN9.1(VBUS) D8.1(A) R39.2 R57.2 R63.2 R64.2 U13.5(VBUS) U16.5(IN)
5V_USB_PWR: D11.1(A)
5V_USB_STLK: C26.2 U16.1(OUT)
EXT_BAT: D7.1(A)
GND: C18.2 C19.1 C20.1 C21.2 C22.1 C23.1 C24.1 C26.1 C28.1 C29.2 C30.2 C31.1 C32.2 C34.1 C36.1 C37.1 C40.1 C41.1 C43.1 C44.1 CN5.3 CN9.5(GND) CN9.6(Shield) CN9.7(Shield) CN9.8(Shield) CN9.9(Shield) CN9.10(EXP) CN9.11(EXP) JP4.2(NO) LD6.1(RED_cathode) R30.2 R36.1 R48.2 R49.2 R51.1 R55.1 R56.1 R60.1 R61.1 SB24.2 U11.4(GND) U11.5(DIR) U12.8(VSSA) U12.20(PB2/BOOT1) U12.23(VSS_1) U12.35(VSS_2) U12.47(VSS_3) U13.2(GND) U14.4(GND) U14.5(DIR) U16.2(GND) U20.2(GND)
UartUsbVbus: D9.1(A)
VBUS: D10.1(A)
AIN_1: R29.2 R55.2 R62.2 U12.10(PA0)
LED_STLK: R50.1 R52.1 U12.30(PA9)
MCO: SB26.2 ; port MCO
NRST: JP2.2(NO) ; port NRST
OSC_IN: C36.2 U12.5(OSCIN) X1.1(X1)
OSC_OUT: C37.2 U12.6(OSCOUT) X1.2(X2)
PA13: SB17.1 ; port TMS/SWDIO
PA14: SB19.1 ; port TCK/SWCLK
PWR_ENn: R63.1 U12.28(PB15) U16.4(~{EN})
STL_USB_D_N: CN9.2(DM) U12.32(PA11) U13.1(IO_1) U13.6(IO1)
STL_USB_D_P: CN9.3(DP) R43.1 U12.33(PA12) U13.3(IO_2) U13.4(IO2)
STLK_RX: R54.1 U14.7(B1) ; port STLK_RX
STLK_TX: JP3.2(NO) U12.12(PA2) ; port STLK_TX
STM_JTCK: SB23.2 U12.37(JTCK/SWCLK)
STM_JTMS: SB21.2 U12.34(JTMS/SWDIO)
STM_RST: C30.1 JP4.1(COMMON) U12.7(NRST)
SWO: SB18.2 ; port SWO
T_JRST: U12.19(PB1)
T_JTCK: R34.2 SB20.1 U12.15(PA5) U12.26(PB13)
T_JTDI: U12.17(PA7)
T_JTDO: U12.16(PA6)
T_JTMS: R32.2 R41.2 SB22.1 U11.6(B2) U12.27(PB14)
T_NRST: JP2.1(COMMON) R31.2 U12.18(PB0)
T_SWDIO_IN: R41.1 U11.3(A2) U12.25(PB12)
T_SWO: R33.2 SB18.1 U11.7(B1)
USB_RENUMn: R37.2 U12.38(PA15/JTDI)
NetC18_1: C18.1 R42.2 SB26.1
NetC34_2: C34.2 U20.4(BYPASS)
NetC40_2: C40.2 C41.2 D7.2(K) D8.2(K) D9.2(K) D10.2(K) D11.2(K) U20.1(Vin) U20.3(CE)
NetCN4_1: CN4.1 SB20.2 SB25.1
NetCN4_2: CN4.2 SB19.2 SB23.1
NetCN4_3: CN4.3 SB22.2 SB24.1
NetCN4_4: CN4.4 SB17.2 SB21.1
NetCN5_1: CN5.1 D1.1(A) R30.1
NetCN5_2: CN5.2 R34.1
NetCN5_4: CN5.4 R32.1
NetCN5_5: CN5.5 R31.1
NetCN5_6: CN5.6 R33.1
NetCN9_4: CN9.4(ID) R48.1
NetD1_2: D1.2(K) R29.1
NetD2_2: D2.2(K) R47.1
NetJP3_1: JP3.1(COMMON) U12.13(PA3) U14.2(A1)
NetLD6_2: LD6.2(Red_anode) R52.2
NetLD6_3: LD6.3(YellowGreen_cathode) R50.2
NetLD7_1: LD7.1 R64.1
NetLD7_2: LD7.2 R57.1 U16.3(~{FAULT})
NetR36_2: R36.2 R37.1 R39.1 T1.1(B)
NetR42_1: R42.1 U12.29(PA8)
NetR43_2: R43.2 T1.2(E)
NetR47_2: R47.2 R49.1 SB29.2 U12.39(PB3/JTDO)
NetR51_2: R51.2 U12.44(BOOT0)
NetR56_2: R56.2 U14.6(B2)
NetR60_2: R60.2 U12.2(PC13)
NetR61_2: R61.2 U12.3(PC14)
NetU11_2: U11.2(A1) U12.31(PA10)

Not connected (* = marked no-connect by the designer): U12 4(PC15)* 11(PA1)* 14(PA4)* 21(PB10)* 22(PB11)* 40(PB4/JNTRST)* 41(PB5)* 42(PB6)* 43(PB7)* 45(PB8)* 46(PB9)*; U14 3(A2)*

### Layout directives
mark named Diff Pair 90ohm: STL_USB_D_N, STL_USB_D_P
differential pair: STL_USB_D_N, STL_USB_D_P

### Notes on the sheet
- TCK/SWCLK
- TMS/SWDIO
- SWD
- (near R60) Board Ident: PC13=0
- PWR_EXT
- SWCLK
- (near CN5) SWD
- SWDIO
- Jumpers ON  --> Discovery Selected
  Jumpers OFF --> ST-LINK Selected
- (near JP3) TX
- (near U20) PWR
- (near JP3) RX
- (near T1) transistor pins numbers follow
  SOT23 JEDEC standard,
- (near CN9) USB ST-LINK
- (near LD6) COM

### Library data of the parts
C18 = MCD-00638: Capacitor, MLCC, 20pF, 50V, NPO, +/-5%, 0603, T=0,8mm; Part_Preference: Recommended; Manufacturer: YAGEO; Manufacturer_Part_Number: CC0603JRNPO9BN200
C19 C20 C23 C26 C28 C30 C31 C41 C43 = MCD-00211: as C25 on sheet Peripherals
C21 C22 C24 C29 = MCD-00237: as C15 on sheet Peripherals
C32 = MCD-00238: Capacitor, MLCC, 1uF, 6V3, X5R, +/-10%, 0603, T=0,8mm; Part_Preference: Recommended; Manufacturer: YAGEO; Manufacturer_Part_Number: CC0603KRX5R5BB105
C34 = MCD-00017: Capacitor, MLCC, 10nF, 50V, X7R, +/-10%, 0603, T=0.8mm; Part_Preference: Recommended; Manufacturer: YAGEO; Manufacturer_Part_Number: CC0603KRX7R9BB103; Order_Code_RS: 616-9537
C36 C37 = MCD-00637: Capacitor, MLCC, 10pF, 50V, NPO, +/-5%, 0603, T=0,8mm; Part_Preference: Recommended; Manufacturer: YAGEO; Manufacturer_Part_Number: CC0603JRNPO9BN100
C40 C44 = MCD-00010: as C63 on sheet Sensors & LCD
CN4 = MCD-00313: Header, 4x1, 2.54mm, VR, TH, Height 6mm/3mm; Part_Type: Connector; Part_Preference: Recommended; Manufacturer: JIUBABA; Manufacturer_Part_Number: PHFS25-11-04-G0B115-T-1; Alternate_Manufacturer: LIANYI; Alternate_Manufacturer_Part_Number: 313104S1411160
CN5 = MCD-00316: Header, 6x1, 2.54mm, VR, TH, Height 6mm/3mm; Part_Type: Connector; Part_Preference: Recommended; Manufacturer: JIUBABA; Manufacturer_Part_Number: PHFS25-11-06-G0B115-T-1; Alternate_Manufacturer: LIANYI; Alternate_Manufacturer_Part_Number: 313106S1411160; Value: Header 1x6
CN9 = MCD-01698: as CN8 on sheet Peripherals
D1 D2 D7-D11 = MCD-00034: BMS_Part_Number: 9151097; Part_Type: Diode; Part_Preference: Recommended; Manufacturer: STMICROELECTRONICS; Manufacturer_HQ_COO: EU
HW5-HW7 = MCD-00043: SHUNT 2.54mm BLACK; Part_Type: Misc; Part_Preference: Recommended; Manufacturer: SAMTEC; Alternate_Manufacturer: JIUBABA; Alternate_Manufacturer_Part_Number: 316102S111A; Value: SNT-100-BK-G
JP2 = MCD-00683: Header, 2x1, 2,54mm, VR, TH, Height 5.84mm/2.54mm - Shunt Fitted by default; Part_Type: Connector; Part_Preference: Recommended; Manufacturer: SAMTEC; Manufacturer_Part_Number: TSW-102-07-G-S; Alternate_Manufacturer: LIANYI; Alternate_Manufacturer_Part_Number: 313102S111116
JP3 JP4 = MCD-00045: Header, 2x1, 2,54mm, VR, TH, Height 5.84mm/2.54mm; Part_Type: Connector; Part_Preference: Recommended; Manufacturer: SAMTEC; Manufacturer_Part_Number: TSW-102-07-G-S; Alternate_Manufacturer: JIUBABA; LIANYI; Alternate_Manufacturer_Part_Number: 313102S111116;313102S111116; Value: Shunt not fitted
LD6 = MCD-00051: LED Bicolor; Part_Type: Display; Part_Preference: Forbidden; Manufacturer: AVAGO TECHNOLOGIES; Manufacturer_Part_Number: HSMF-A201-A00J1; Alternate_Manufacturer: EVERLUCK; Alternate_Manufacturer_Part_Number: LE-RGW35280
LD7 = MCD-00049: LED, Red, 0603; Part_Type: Display; Part_Preference: Recommended; Manufacturer: EVERLIGHT; Manufacturer_Part_Number: 19-213-R6C-AP1Q2B/3T
R29 R31-R34 = MCD-00066: Resistor,22R,0603,1%,1/10W; Part_Preference: Recommended; Manufacturer: YAGEO; Manufacturer_Part_Number: RC0603FR-0722RL
R30 R39 R56 R60 R61 = MCD-00220: as R40 on sheet Peripherals
R36 = MCD-00221: Resistor,36K,0603,1%,1/10W; Part_Preference: Recommended; Manufacturer: YAGEO; Manufacturer_Part_Number: RC0603FR-0736KL
R37 R41 R42 = MCD-00224: Resistor,100R,0603,1%,1/10W; Part_Preference: Recommended; Manufacturer: YAGEO; Manufacturer_Part_Number: RC0603FR-07100RL
R43 = MCD-00217: Resistor,1K5,0603,1%,1/10W; BMS_Part_Number: 9129766; Part_Preference: Recommended; Manufacturer: YAGEO; Manufacturer_Part_Number: RC0603FR-071K5L
R47 = MCD-00218: Resistor,2K7,0603,1%,1/10W; BMS_Part_Number: 9129767; Part_Preference: Recommended; Manufacturer: YAGEO; Manufacturer_Part_Number: RC0603FR-072K7L
R48 R51 R54 = MCD-00223: as R46 on sheet Peripherals
R49 = MCD-00219: Resistor,4K7,0603,1%,1/10W; Part_Preference: Recommended; Manufacturer: YAGEO; Manufacturer_Part_Number: RC0603FR-074K7L
R50 R52 = MCD-00197: Resistor,330R,0603,1%,1/10W; BMS_Part_Number: 9129729; Part_Preference: Recommended; Manufacturer: YAGEO; Manufacturer_Part_Number: RC0603FR-07330RL
R55 R62 = MCD-00257: as R18 on sheet Sensors & LCD
R57 R63 = MCD-00222: as R90 on sheet Peripherals
R64 = MCD-00070: Resistor,1K,0603,1%,1/10W; Part_Preference: Recommended; Manufacturer: YAGEO; Manufacturer_Part_Number: RC0603FR-071KL
SB17-SB20 SB22 SB36 = MCD-00071: as SB7 on sheet Sensors & LCD
SB21 SB23-SB26 SB29 SB35 = MCD-00072: as SB13 on sheet Sensors & LCD
T1 = MCD-00073: NPN Bipolar Transistor; Part_Type: IC; Part_Preference: Recommended; Manufacturer: ON SEMICONDUCTOR; Manufacturer_Part_Number: BSR14; Alternate_Manufacturer_Part_Number: MMBT2222LT1G / MMBT2222ALT1G / MMBT2222ALT3G; Value: NPN SOT23
U11 U14 = MCD-00264: Dual bit dual supply bus transceiver; BMS_Part_Number: 9169311; Part_Type: IC; Part_Preference: Recommended; Manufacturer: TEXAS INSTRUMENTS
U12 = MCD-00085: Medium-density performance line ARM-based 32-bit MCU with 128KB Flash; BMS_Part_Number: 9175111; Part_Type: IC; Part_Preference: Recommended; Manufacturer: STMICROELECTRONICS; Manufacturer_HQ_COO: EU
U13 = MCD-00163: as U9 on sheet Peripherals
U16 = MCD-00083: Enhanced single channel power switches with active low enable pin; BMS_Part_Number: 9159003; Part_Type: IC; Part_Preference: Recommended; Manufacturer: STMICROELECTRONICS; Alternate_Manufacturer: TEXAS INSTRUMENTS; Alternate_Manufacturer_Part_Number: TPS2041C; Manufacturer_HQ_COO: EU
U20 = MCD-00086: Ultra low drop-low noise BiCMOS voltage, regulators low ESR capacitors compatible; BMS_Part_Number: 9176161; Part_Type: IC; Part_Preference: Recommended; Manufacturer: STMICROELECTRONICS; Manufacturer_HQ_COO: EU
X1 = MCD-00092: Crystal 8MHz, 8pF, +-20ppm, 500ohms max,  SMD; BMS_Part_Number: 9157029; Part_Type: Crystal oscillator; Part_Preference: Recommended; Manufacturer: NDK; Manufacturer_Part_Number: NX3225GD 8MHz EXS00A-CG04874

## Sheet Other.SchDoc: Other
size A4; Date: Not used; ApprovedBy: Not used; CheckedBy: Not used; Author: Not used; CompanyName: STMicroelectronics; DrawnBy: Not used; Engineer: Not used; Organization: Not used; Address1: Not used; Address2: Not used; Address3: Not used; Address4: Not used; DocumentNumber: Not used; Revision: Not used; SheetNumber: 12; SheetTotal: 12
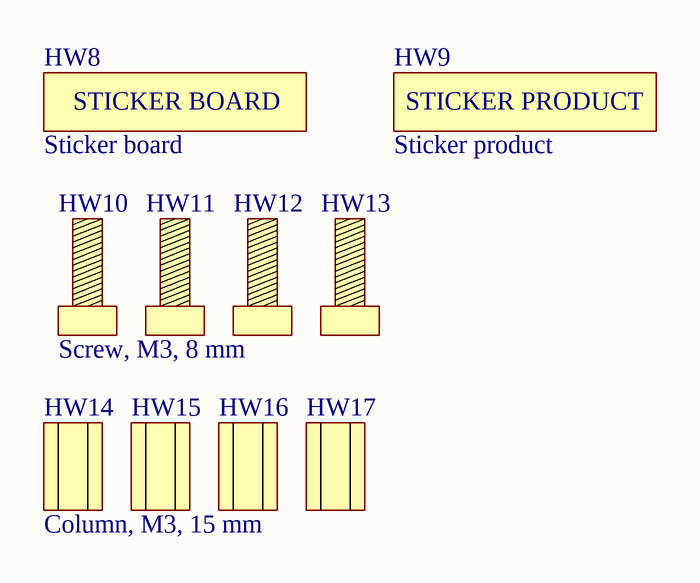
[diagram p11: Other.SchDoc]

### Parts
HW8  value Sticker board  [STICKER_BOARD_25X9]  (hidden comment: STICKER_BOARD)  (no BOM)
HW9  value Sticker product  [STICKER_PRODUCT_25X9]  (hidden comment: STICKER_PRODUCT)  (no BOM)
HW10  value Screw, M3, 8 mm  (hidden comment: SCREW)  (mechanical)
HW11  SCREW  (value not drawn)  (mechanical)
HW12  SCREW  (value not drawn)  (mechanical)
HW13  SCREW  (value not drawn)  (mechanical)
HW14  value Column, M3, 15 mm  (hidden comment: PILLAR_SMALL)  (mechanical)
HW15  PILLAR_SMALL  (value not drawn)  (mechanical)
HW16  PILLAR_SMALL  (value not drawn)  (mechanical)
HW17  PILLAR_SMALL  (value not drawn)  (mechanical)

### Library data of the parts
HW8 = MCD-00235: Sticker Board 25x9 mm; Part_Type: Misc; Part_Preference: Recommended
HW9 = MCD-00547: Sticker product 25x9 mm; Part_Type: Misc; Part_Preference: Recommended
HW10-HW13 = MCD-01901: Nylon screw, M3, 8 mm; Part_Type: Accessory; Part_Preference: Forbidden; Manufacturer: SOLY; Manufacturer_Part_Number: PF3-8N
HW14-HW17 = MCD-01900: Column, M3, 15 mm; Part_Type: Accessory; Part_Preference: Forbidden; Manufacturer: SOLY; Manufacturer_Part_Number: HTP-315

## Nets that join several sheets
1V8: Power (SB33.2 SB34.2 TP24.1), 1SE_Modem (CN12.48 R10.2 R13.2), VoLTE (8 pins), Uart2USB (12 pins), SIM (R8.2), 1SE_MCU (SB39.2), Extension connectors (14 pins), Peripherals (C15.2 CN3.1 R40.1 U8.8), Sensors & LCD (10 pins), ST_LINK_V2-1 (SB36.2)
1V8_MD: Power (Q3.1 R58.2 SB33.1), 1SE_Modem (6 pins), 1SE_MCU (R1.2 R74.2 R82.2 SB4.2), Sensors & LCD (6 pins), ST_LINK_V2-1 (R62.1 SB35.2)
3V3: Power (5 pins), 1SE_Modem (CN13.42 R15.2 R17.2), 1SE_MCU (5 pins), Extension connectors (8 pins), Peripherals (R88.2 R98.2 R118.2)
3V6: Power (5 pins), Sensors & LCD (C74.2 U1.5)
5V: Power (14 pins), 1SE_Modem (CN13.50), Extension connectors (P1.6 P1.15), ST_LINK_V2-1 (D2.1)
5V_USB_PWR: Power (CN11.1 D12.1 U21.1), ST_LINK_V2-1 (D11.1)
5V_USB_STLK: Power (D3.1), ST_LINK_V2-1 (C26.2 U16.1)
AVDD: 1SE_Modem (CN12.1), 1SE_MCU (C50.1 L1.1 TP17.1 U5.5)
EXT_BAT: Power (BT1.1 D4.1), ST_LINK_V2-1 (D7.1)
GND: Power (38 pins), 1SE_Modem (57 pins), VoLTE (28 pins), Uart2USB (28 pins), SIM (11 pins), 1SE_MCU (13 pins), Extension connectors (14 pins), Peripherals (21 pins), Sensors & LCD (32 pins), ST_LINK_V2-1 (52 pins)
UartUsbVbus: Power (D5.1), Uart2USB (6 pins), ST_LINK_V2-1 (D9.1)
VBUS: Power (D6.1), Peripherals (C25.2 CN8.1 U9.5), ST_LINK_V2-1 (D10.1)
VDD_MD: Power (JP1.2 TP13.1), 1SE_Modem (5 pins)
VDD_SIM: 1SE_Modem (CN13.13 TP11.1 U5.50), SIM (5 pins)
VDDIO_MDM: 1SE_Modem (CN13.2 U5.30), VoLTE (SB48.1)
FFU_CLKOUT: 1SE_Modem (CN13.17 U5.38), VoLTE (SB47.1)
FFU_I2C0_SCL: 1SE_Modem (CN13.1 R13.1 U5.66), VoLTE (R91.1)
FFU_I2C0_SDA: 1SE_Modem (CN13.3 R10.1 U5.67), VoLTE (R93.1)
FFU_PCM_CLK: 1SE_Modem (CN13.27 U5.34), VoLTE (U24.30)
FFU_PCM_FS: 1SE_Modem (CN13.25 U5.32), VoLTE (U24.29)
FFU_PCM_IN: 1SE_Modem (CN13.21 U5.33), VoLTE (U24.27)
FFU_PCM_OUT: 1SE_Modem (CN13.23 U5.31), VoLTE (U24.28)
I2C1_SCL: 1SE_Modem (CN12.20), 1SE_MCU (U5.70), Extension connectors (R109.2 U29.4), Sensors & LCD (R24.1 R28.1 R35.1 R99.2)
I2C1_SDA: 1SE_Modem (CN12.22), 1SE_MCU (U5.69), Extension connectors (R108.2 U29.5), Sensors & LCD (R23.1 R25.1 R38.1 R100.2)
ISOLATION_CTRL: 1SE_Modem (LD4.2 Q6.3), Uart2USB (U15.1 U15.19)
MCO: 1SE_Modem (CN12.47), 1SE_MCU (U5.55), Extension connectors (U27.8), ST_LINK_V2-1 (SB26.2)
NC_RST_IND: 1SE_Modem (CN13.20 R73.1 U5.11), 1SE_MCU (SB37.2)
NC_SIM_CLK: 1SE_Modem (CN13.7 U5.49), SIM (R5.1)
NC_SIM_DETECT: 1SE_Modem (CN13.15 U5.52), SIM (SB5.2)
NC_SIM_IO: 1SE_Modem (CN13.11 U5.57), SIM (R4.1 R7.1)
NC_SIM_RST: 1SE_Modem (CN13.9 U5.53), SIM (R6.1)
NRST: 1SE_MCU (5 pins), Peripherals (R12.2), ST_LINK_V2-1 (JP2.2)
PA0: 1SE_Modem (CN12.3), 1SE_MCU (U5.4), Extension connectors (U28.1)
PA1: 1SE_Modem (CN12.5), 1SE_MCU (U5.1), Extension connectors (U28.3)
PA2: 1SE_Modem (CN12.7), 1SE_MCU (U5.3), Extension connectors (U28.4)
PA3: 1SE_Modem (CN12.9), 1SE_MCU (U5.2), Extension connectors (U28.5)
PA4: 1SE_Modem (CN12.11), 1SE_MCU (U5.82)
PA5: 1SE_Modem (CN12.13), 1SE_MCU (U5.72), Extension connectors (U28.6)
PA6: 1SE_Modem (CN12.15), 1SE_MCU (U5.100), Peripherals (TP16.1 U8.7)
PA7: 1SE_Modem (CN12.17), 1SE_MCU (U5.101), Peripherals (TP18.1 U8.3)
PA8: 1SE_Modem (CN12.21), 1SE_MCU (U5.65), Extension connectors (U28.7)
PA9: 1SE_Modem (CN12.23), 1SE_MCU (SB44.2 U5.90)
PA10: 1SE_Modem (CN12.25), 1SE_MCU (SB46.2 U5.89)
PA11: 1SE_Modem (CN12.27), 1SE_MCU (U5.88), Peripherals (CN8.2 U9.1 U9.6)
PA12: 1SE_Modem (CN12.29), 1SE_MCU (U5.87), Peripherals (CN8.3 U9.3 U9.4)
PA13: 1SE_Modem (CN12.31), 1SE_MCU (U5.86), Peripherals (R81.1), ST_LINK_V2-1 (SB17.1)
PA14: 1SE_Modem (CN12.33), 1SE_MCU (U5.85), Peripherals (R83.1), ST_LINK_V2-1 (SB19.1)
PA15: 1SE_Modem (CN12.35), 1SE_MCU (U5.75), Extension connectors (U28.8)
PB0: 1SE_Modem (CN12.2), 1SE_MCU (U5.99), Peripherals (TP14.1 U8.2)
PB1: 1SE_Modem (CN12.4), 1SE_MCU (U5.95), Peripherals (TP19.1 U8.5)
PB2_R: 1SE_Modem (CN12.6), 1SE_MCU (U5.83), Sensors & LCD (R72.1 U1.11)
PB3: 1SE_Modem (CN12.8), 1SE_MCU (SB40.2 U5.76)
PB4: 1SE_Modem (CN12.12), 1SE_MCU (U5.74), Extension connectors (U29.1)
PB5: 1SE_Modem (CN12.14), 1SE_MCU (U5.73), Extension connectors (U29.3)
PB6: 1SE_Modem (CN12.16), 1SE_MCU (SB3.1 U5.64)
PB7_R: 1SE_Modem (CN12.18), 1SE_MCU (U5.48)
PB10: 1SE_Modem (CN12.24), 1SE_MCU (U5.96), Peripherals (TP15.1 U8.6)
PB11: 1SE_Modem (CN12.26), 1SE_MCU (SB28.2 SB43.1 U5.97)
PB14: 1SE_Modem (CN12.28), 1SE_MCU (U5.92), Extension connectors (SB49.1), Peripherals (R90.2)
PB15: 1SE_Modem (CN12.32), 1SE_MCU (U5.91), Peripherals (R101.2)
PC0: 1SE_Modem (CN12.37), 1SE_MCU (U5.58), Extension connectors (SB53.1 SB59.1)
PC1: 1SE_Modem (CN12.41), 1SE_MCU (U5.60), Extension connectors (U27.3)
PC2: 1SE_Modem (CN12.43), 1SE_MCU (U5.59), Sensors & LCD (SB14.1 SB15.1)
PC3: 1SE_Modem (CN12.45), 1SE_MCU (U5.61), Sensors & LCD (SB10.1)
PC6: 1SE_Modem (CN12.34), 1SE_MCU (U5.94), Peripherals (R113.2)
PC7: 1SE_Modem (CN12.36), 1SE_MCU (SB37.1 U5.10)
PC9: 1SE_Modem (CN12.38), 1SE_MCU (U5.93), Extension connectors (U27.4)
PC10: 1SE_Modem (CN12.40), 1SE_MCU (U5.80), Extension connectors (U27.5), Sensors & LCD (U1.14)
PC11: 1SE_Modem (CN12.42), 1SE_MCU (U5.77), Extension connectors (U27.6), Sensors & LCD (U1.13)
PC12: 1SE_Modem (CN12.44), 1SE_MCU (U5.78), Extension connectors (U27.7), Sensors & LCD (U1.15)
PC13: 1SE_Modem (CN12.46), 1SE_MCU (SB2.1 U5.62)
PH1: 1SE_Modem (CN12.49), 1SE_MCU (U5.54), Sensors & LCD (R96.2)
PH3: 1SE_Modem (CN12.50), 1SE_MCU (R11.2 U5.63)
QSPI_NCS: 1SE_MCU (SB28.1), Peripherals (R40.2 TP20.1 U8.1)
RFT_UART1_CTS: 1SE_Modem (CN13.33 U5.26), Uart2USB (U15.17)
RFT_UART1_RTS: 1SE_Modem (CN13.35 U5.23), Uart2USB (U18.29)
RFT_UART1_RX: 1SE_Modem (CN13.31 U5.25), Uart2USB (U15.18)
RFT_UART1_TX: 1SE_Modem (CN13.29 U5.24), Uart2USB (U18.2)
RFT_UART2_CTS: 1SE_Modem (CN13.43 U5.16), Uart2USB (U15.13)
RFT_UART2_RTS: 1SE_Modem (CN13.45 U5.18), Uart2USB (U18.8)
RFT_UART2_RX: 1SE_Modem (CN13.41 U5.19), Uart2USB (SB31.1 SB32.2 U17.B1 U17.C2)
RFT_UART2_TX: 1SE_Modem (CN13.37 U5.17), Uart2USB (SB30.2 SB31.2)
SF_EN: 1SE_Modem (R122.1 R123.1 SB6.2), 1SE_MCU (SB3.2)
STLK_RX: 1SE_MCU (SB44.1), ST_LINK_V2-1 (R54.1 U14.7)
STLK_TX: 1SE_MCU (SB46.1), ST_LINK_V2-1 (JP3.2 U12.12)
SWO: 1SE_MCU (SB40.1), Peripherals (R75.2), ST_LINK_V2-1 (SB18.2)

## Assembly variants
L462RE: not fitted B3 C7 C18 C53 C54 C56 C62 C67 C78 C79 CN3 CN7 R9 R14 R16 R18 R20 R22 R29 R41 R44 R61 R73 R74 R77 R78 R84 R85 R86 R87 R89 R112 R115 R120 R121 R123 SB6 SB13 SB14 SB21 SB23 SB24 SB25 SB26 SB28 SB29 SB31 SB32 SB33 SB35 SB39 SB41 SB51 SB54 SB55 SB56 SB59 X2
